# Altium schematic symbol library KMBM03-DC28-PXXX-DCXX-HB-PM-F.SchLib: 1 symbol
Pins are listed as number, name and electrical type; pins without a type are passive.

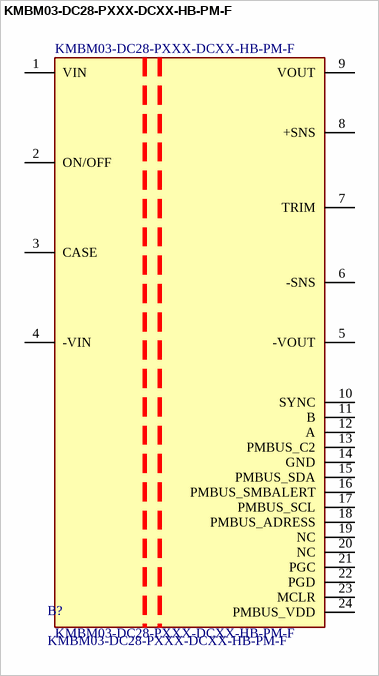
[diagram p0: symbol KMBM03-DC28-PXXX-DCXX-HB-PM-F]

## KMBM03-DC28-PXXX-DCXX-HB-PM-F
designator B?
16-40Vin XXVout XXXW Isolated Half Brick with Flanged Option; MFG: KOLT
footprint KMBM03-DC28-PXXX-DCXX-HB-PM-F
pins: 1 VIN, 2 ON/OFF, 3 CASE, 4 -VIN, 5 -VOUT, 6 -SNS, 7 TRIM, 8 +SNS, 9 VOUT, 10 SYNC, 11 B, 12 A, 13 PMBUS_C2, 14 GND, 15 PMBUS_SDA, 16 PMBUS_SMBALERT, 17 PMBUS_SCL, 18 PMBUS_ADRESS, 19 NC, 20 NC, 21 PGC, 22 PGD, 23 MCLR, 24 PMBUS_VDD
